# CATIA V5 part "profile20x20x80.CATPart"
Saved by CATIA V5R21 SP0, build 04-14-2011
Part number: 80
Bounding box of the stored display mesh (mm): x -24.289 to -4.289, y -1.335 to 18.665, z 0 to 80
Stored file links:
  C:\Users\2027.DESARCY-LEMIE30\Desktop\Assemblage26.05\profile20x20x80.CATPart
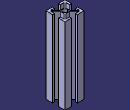
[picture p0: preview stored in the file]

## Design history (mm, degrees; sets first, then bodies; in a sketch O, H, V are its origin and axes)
Body1 (main body)
  Sketch1 on xy-plane, origin (0, 0, 0), H (1, 0, 0), V (0, 1, 0)
    point P1 (-17.2892, 11.6647)
    line L1 (-16.2892, 11.6647) -> (-12.2892, 11.6647)
    point P2 (-11.2892, 11.6647)
    line L2 (-11.2892, 10.6647) -> (-11.2892, 6.6647)
    point P3 (-11.2892, 5.6647)
    line L3 (-12.2892, 5.6647) -> (-16.2892, 5.6647)
    point P4 (-17.2892, 5.6647)
    line L4 (-17.2892, 6.6647) -> (-17.2892, 10.6647)
    point P5 (-24.2892, 18.6647)
    point P6 (-4.2892, 18.6647)
    point P7 (-4.2892, -1.3353)
    line L5 (-11.1892, 18.6647) -> (-11.1892, 16.6647)
    point P8 (-11.1892, 18.6647)
    point P10 (-11.1892, 18.6647)
    point P11 (-17.3892, 18.6647)
    line L6 (-17.3892, 18.6647) -> (-17.3892, 16.6647)
    point P12 (-17.3892, 18.6647)
    line L7 (-11.1892, 18.6647) -> (-4.2892, 18.6647)
    point P14 (-11.1892, 18.6647)
    point P15 (-4.2892, 18.6647)
    point P16 (-11.1892, -1.3353)
    point P17 (-17.3892, -1.3353)
    line L8 (-17.3892, -1.3353) -> (-17.3892, 0.6647)
    point P18 (-17.3892, -1.3353)
    line L9 (-11.1892, -1.3353) -> (-11.1892, 0.6647)
    point P20 (-11.1892, -1.3353)
    line L10 (-24.2892, -1.3353) -> (-17.3892, -1.3353)
    point P22 (-24.2892, -1.3353)
    point P23 (-17.3892, -1.3353)
    line L11 (-11.1892, -1.3353) -> (-4.2892, -1.3353)
    point P24 (-11.1892, -1.3353)
    point P25 (-4.2892, -1.3353)
    line L12 (-24.2892, 18.6647) -> (-17.3892, 18.6647)
    point P26 (-24.2892, 18.6647)
    point P27 (-17.3892, 18.6647)
    point P28 (-4.2892, 5.5647)
    point P29 (-4.2892, 11.7647)
    line L13 (-6.2892, 11.7647) -> (-4.2892, 11.7647)
    point P31 (-4.2892, 11.7647)
    line L14 (-4.2892, 5.5647) -> (-6.2892, 5.5647)
    point P32 (-4.2892, 5.5647)
    point P34 (-24.2892, 5.5647)
    point P35 (-24.2892, 11.7647)
    line L15 (-24.2892, 11.7647) -> (-22.2892, 11.7647)
    point P36 (-24.2892, 11.7647)
    line L16 (-24.2892, 5.5647) -> (-22.2892, 5.5647)
    point P38 (-24.2892, 5.5647)
    line L17 (-4.2892, 18.6647) -> (-4.2892, 11.7647)
    point P40 (-4.2892, 18.6647)
    point P41 (-4.2892, 11.7647)
    line L18 (-24.2892, 18.6647) -> (-24.2892, 11.7647)
    point P42 (-24.2892, 18.6647)
    point P43 (-24.2892, 11.7647)
    line L19 (-24.2892, -1.3353) -> (-24.2892, 5.5647)
    point P44 (-24.2892, -1.3353)
    point P45 (-24.2892, 5.5647)
    line L20 (-4.2892, -1.3353) -> (-4.2892, 5.5647)
    point P46 (-4.2892, -1.3353)
    point P47 (-4.2892, 5.5647)
    line L21 (-22.2892, 5.5647) -> (-22.2892, 1.6647)
    line L22 (-21.2892, 0.6647) -> (-17.3892, 0.6647)
    line L23 (-6.2892, 5.5647) -> (-6.2892, 1.6647)
    line L24 (-11.1892, 0.6647) -> (-7.2892, 0.6647)
    line L25 (-11.1892, 16.6647) -> (-7.2892, 16.6647)
    line L26 (-6.2892, 15.6647) -> (-6.2892, 11.7647)
    line L27 (-17.3892, 16.6647) -> (-21.2892, 16.6647)
    line L28 (-22.2892, 15.6647) -> (-22.2892, 11.7647)
    point P48 (-16.2892, 11.6647)
    point P49 (-17.2892, 10.6647)
    point P50 (-17.2892, 6.6647)
    point P52 (-11.2892, 6.6647)
    point P53 (-11.2892, 10.6647)
    point P54 (-12.2892, 11.6647)
    point P55 (-12.2892, 5.6647)
    line L29 (-16.2892, 11.6647) -> (-21.2892, 16.6647)
    line L30 (-17.2892, 10.6647) -> (-22.2892, 15.6647)
    line L31 (-12.2892, 11.6647) -> (-7.2892, 16.6647)
    line L32 (-16.2892, 5.6647) -> (-21.2892, 0.6647)
    line L33 (-17.2892, 6.6647) -> (-22.2892, 1.6647)
    line L34 (-12.2892, 5.6647) -> (-7.2892, 0.6647)
    line L35 (-11.2892, 6.6647) -> (-6.2892, 1.6647)
    line L36 (-11.2892, 10.6647) -> (-6.2892, 15.6647)
    length L5 = 2
    distance P10 P6 = 6.9
    length L6 = 2
    length L8 = 2
    length L9 = 2
    distance P7 P28 = 6.9
    distance P6 P29 = 6.9
    length L13 = 2
    length L14 = 2
    length L15 = 2
    distance P5 P42 = 0
    length L11 = 6.9
    distance P46 P7 = 0
    distance P1 P48 = 1
    distance P49 P1 = 1
    distance P4 P50 = 1
    distance P54 P2 = 1
    distance P2 P3 = 6
    distance P1 P2 = 6
    horizontal: L1 H, L3 H, L7 H, L10 H, L11 H, L12 H, L13 H, L14 H, L15 H, L16 H, L22 H, L24 H, L25 H, L27 H
    vertical: L2 V, L4 V, L5 V, L6 V, L8 V, L9 V, L17 V, L18 V, L19 V, L20 V, L21 V, L23 V, L26 V, L28 V
    coincidence: P10 P8, P11 P12, P6 P15, P8 P14, P16 L5, P17 L6, P17 P18, P16 P20, P23 L8, P24 L9, P20 P24, P27 L6, P5 P26, P29 P31, P28 P32, P34 L14, P35 L13, P34 P38, P35 P36, P40 L7, P41 L13, P6 P40, P42 L7, P43 L13, P44 L11, P45 L14, P38 P45, P46 L11, P47 L14, P49 L4, P50 L4, P52 L2, P53 L2, P55 L3, P22 P44, P25 P46
    fix: P34, P12, P5, P36, P55
  Pad1: profile Sketch1, direction (0, 0, 1), length 80
  Sketch2 on end face of Pad1, origin (0, 0, 80), H (1, 0, 0), V (0, 1, 0)
    circle A1 centre (-14.2892, 8.6647) radius 2.5
    point P1 (-14.2892, 8.6647)
    reference projected line E1 (-12.2892, 11.6647) -> (-16.2892, 11.6647) from edge [face of Pad1 from Sketch1.L1 | end face of Pad1]
    reference projected line E2 (-11.2892, 6.6647) -> (-11.2892, 10.6647) from edge [face of Pad1 from Sketch1.L2 | end face of Pad1]
    radius A1 = 2.5
    distance P1 E1 = 3
    distance P1 E2 = 3
  Pocket1: profile Sketch2, direction (0, 0, -1), length 105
